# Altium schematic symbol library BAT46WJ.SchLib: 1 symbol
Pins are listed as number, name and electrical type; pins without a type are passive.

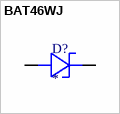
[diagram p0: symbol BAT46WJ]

## BAT46WJ
designator D?
Diode Schottky 100V 250mA (DC) Surface Mount SOD-323F; MP: BAT46WJ; MF: NXP Semiconductors
footprint BAT46WJ
pins: A "Anode", C "Cathode"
